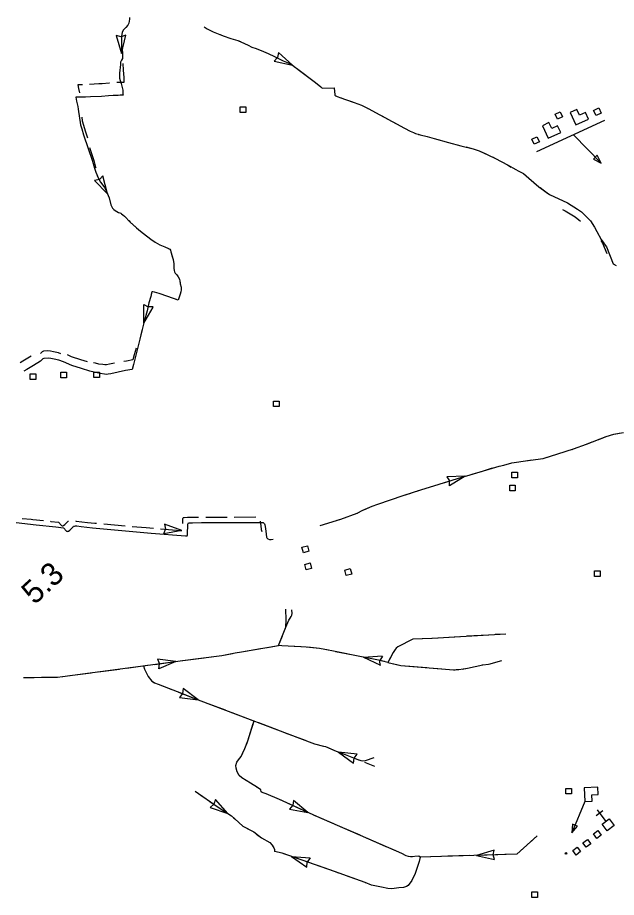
# Model space of a CAD drawing. Extents: x -160 to 6143532, y -375 to 762199.
# Drawn here: x -110.03 to -87.11, y -272.42 to -238.77 of the extents above; entities that cross this region are included whole.
import ezdxf

# ---------------------------------------------------------------- set-up
doc = ezdxf.new("R2010")
doc.units = 0
for name, color, linetype in [('Level 43', 7, 'Continuous'), ('Level 48', 7, 'Continuous'), ('Level 56', 7, 'Continuous'), ('Level 57', 7, 'Continuous'), ('Level 58', 7, 'Continuous')]:
    doc.layers.add(name, color=color, linetype=linetype)

msp = doc.modelspace()

# ---------------------------------------------------------------- linework, layer by layer
at = {"layer": 'Level 43'}
for p, q in [((-106.066, -239.503), (-106.25, -239.46)), ((-106.25, -239.46), (-106.046, -240.14)), ((-105.883, -239.449), (-106.064, -239.503)), ((-106.046, -240.14), (-105.883, -239.449)), ((-100.039, -240.112), (-100.079, -240.296)), ((-99.513, -240.588), (-100.039, -240.112)), ((-100.08, -240.298), (-100.207, -240.439)), ((-100.207, -240.439), (-99.513, -240.588)), ((-106.761, -244.829), (-106.896, -244.961)), ((-106.588, -245.518), (-106.761, -244.829)), ((-106.899, -244.962), (-107.082, -245.008)), ((-107.082, -245.008), (-106.588, -245.518)), ((-105.203, -249.75), (-105.036, -249.838)), ((-105.198, -250.454), (-105.192, -249.744)), ((-105.198, -250.454), (-104.838, -249.842)), ((-104.845, -249.832), (-105.033, -249.839)), ((-92.895, -256.305), (-93.604, -256.333)), ((-93.604, -256.333), (-93.503, -256.493)), ((-92.895, -256.305), (-93.495, -256.684)), ((-93.495, -256.684), (-93.503, -256.495)), ((-104.437, -258.517), (-104.373, -258.339)), ((-103.738, -258.391), (-104.437, -258.517)), ((-103.738, -258.391), (-104.406, -258.151)), ((-104.406, -258.151), (-104.373, -258.336)), ((-103.969, -263.401), (-104.673, -263.309)), ((-104.673, -263.309), (-104.6, -263.483)), ((-103.969, -263.401), (-104.624, -263.673)), ((-96.784, -263.235), (-96.076, -263.183)), ((-96.784, -263.235), (-96.145, -263.544)), ((-96.067, -263.19), (-96.159, -263.356)), ((-96.156, -263.547), (-96.159, -263.358)), ((-104.624, -263.673), (-104.6, -263.485)), ((-103.692, -264.437), (-103.714, -264.624)), ((-103.123, -264.861), (-103.692, -264.437)), ((-103.715, -264.627), (-103.828, -264.778)), ((-103.828, -264.778), (-103.123, -264.861)), ((-97.036, -266.946), (-97.741, -266.864)), ((-97.741, -266.864), (-97.171, -267.287)), ((-97.171, -267.287), (-97.15, -267.1)), ((-97.149, -267.097), (-97.036, -266.946)), ((-102.451, -268.671), (-102.513, -268.85)), ((-101.986, -269.208), (-102.451, -268.671)), ((-99.464, -268.71), (-99.498, -268.896)), ((-98.923, -269.169), (-99.464, -268.71)), ((-102.514, -268.852), (-102.657, -268.976)), ((-102.657, -268.976), (-101.986, -269.208)), ((-99.499, -268.898), (-99.622, -269.042)), ((-99.622, -269.042), (-98.923, -269.169)), ((-99.542, -270.859), (-98.955, -271.258)), ((-99.542, -270.859), (-98.834, -270.911)), ((-91.787, -270.609), (-92.466, -270.815)), ((-92.466, -270.815), (-91.775, -270.976)), ((-91.83, -270.793), (-91.787, -270.609)), ((-91.775, -270.976), (-91.83, -270.796)), ((-98.955, -271.258), (-98.941, -271.07)), ((-98.834, -270.911), (-98.941, -271.067))]:
    msp.add_line(p, q, dxfattribs=at)
for points in [[(-105.744, -238.772), (-105.748, -238.836), (-105.777, -238.984), (-105.805, -239.063), (-105.882, -239.146), (-105.982, -239.25), (-106.026, -239.338), (-106.055, -239.48), (-106.055, -239.593), (-106.051, -239.811), (-106.02, -240.105), (-106.014, -240.298), (-106.02, -240.343), (-106.048, -240.396), (-106.087, -240.478), (-106.093, -240.567), (-106.129, -240.898), (-106.13, -241.018), (-106.125, -241.088), (-106.107, -241.184), (-106.062, -241.295), (-105.995, -241.548), (-105.995, -241.688), (-105.992, -241.739), (-106.097, -241.742), (-106.183, -241.748), (-106.265, -241.75), (-106.369, -241.75), (-106.549, -241.762), (-106.821, -241.785), (-107.242, -241.804), (-107.425, -241.81), (-107.794, -241.821), (-107.779, -241.964), (-107.72, -242.177), (-107.71, -242.28), (-107.616, -242.869), (-107.575, -243.032), (-107.507, -243.251), (-107.162, -244.264), (-107.091, -244.53), (-107.035, -244.685), (-106.937, -244.925), (-106.854, -245.063), (-106.809, -245.136), (-106.708, -245.274), (-106.624, -245.427), (-106.526, -245.67), (-106.458, -245.935), (-106.426, -246.009), (-106.393, -246.065), (-106.373, -246.087), (-106.344, -246.115), (-106.296, -246.147), (-106.163, -246.226), (-106.122, -246.242), (-106.079, -246.255), (-106.052, -246.273), (-105.996, -246.316), (-105.937, -246.372), (-105.715, -246.591), (-105.386, -246.893), (-105.212, -247.033), (-104.929, -247.243), (-104.758, -247.36), (-104.583, -247.459), (-104.398, -247.545), (-104.255, -247.604), (-104.208, -247.633), (-104.18, -247.667), (-104.159, -247.732), (-104.074, -248.023), (-104.054, -248.189), (-104.051, -248.36), (-104.041, -248.442), (-104.023, -248.5), (-103.995, -248.551), (-103.939, -248.606), (-103.883, -248.683), (-103.838, -248.778), (-103.816, -248.853), (-103.802, -248.957), (-103.773, -249.078), (-103.765, -249.185)], [(-105.744, -238.772), (-105.748, -238.836), (-105.752, -238.858)], [(-105.847, -239.108), (-105.882, -239.146), (-105.982, -239.25), (-106.026, -239.338), (-106.055, -239.48), (-106.055, -239.593), (-106.051, -239.811), (-106.046, -239.859), (-106.046, -240.14)], [(-102.885, -239.125), (-102.772, -239.207), (-102.544, -239.313), (-102.165, -239.47), (-101.865, -239.568), (-101.594, -239.652), (-101.34, -239.761), (-101.2, -239.826), (-101.063, -239.903), (-100.903, -239.949), (-100.62, -240.072), (-100.443, -240.147), (-100.19, -240.264), (-99.968, -240.376), (-99.861, -240.424), (-99.67, -240.506), (-99.52, -240.582), (-99.449, -240.637), (-99.305, -240.749), (-98.675, -241.217), (-98.5, -241.355), (-98.424, -241.424), (-98.378, -241.471), (-97.907, -241.46), (-97.892, -241.724), (-97.881, -241.74), (-97.853, -241.763), (-97.794, -241.791), (-97.523, -241.886), (-97.144, -242.015), (-96.872, -242.126), (-96.606, -242.255), (-96.159, -242.491), (-95.218, -243.001), (-94.999, -243.11), (-94.871, -243.168), (-94.797, -243.199), (-94.702, -243.231), (-94.615, -243.258), (-94.349, -243.314), (-94.079, -243.394), (-93.538, -243.552)], [(-102.885, -239.125), (-102.772, -239.207), (-102.544, -239.313), (-102.527, -239.32)], [(-102.275, -239.424), (-102.165, -239.47), (-101.865, -239.568), (-101.594, -239.652), (-101.501, -239.692)], [(-101.252, -239.802), (-101.2, -239.826), (-101.063, -239.903), (-100.903, -239.949), (-100.62, -240.072), (-100.5, -240.123)], [(-100.251, -240.235), (-100.19, -240.264), (-99.968, -240.376), (-99.861, -240.424), (-99.67, -240.506), (-99.52, -240.582), (-99.513, -240.588)], [(-106.006, -240.524), (-105.986, -240.779), (-105.965, -241.058), (-105.965, -241.198), (-105.962, -241.249), (-106.068, -241.252), (-106.153, -241.258), (-106.227, -241.26)], [(-99.296, -240.755), (-98.675, -241.217), (-98.64, -241.245)], [(-107.545, -241.342), (-107.719, -241.347), (-107.703, -241.49), (-107.66, -241.644)], [(-106.506, -241.279), (-106.526, -241.28), (-106.797, -241.303), (-106.914, -241.309), (-107.28, -241.329)], [(-97.641, -241.845), (-97.523, -241.886), (-97.253, -241.978)], [(-97.253, -241.978), (-97.144, -242.015), (-96.872, -242.126), (-96.871, -242.126)], [(-96.626, -242.245), (-96.606, -242.255), (-96.159, -242.491), (-95.903, -242.63)], [(-107.575, -242.581), (-107.552, -242.725), (-107.512, -242.888), (-107.443, -243.108), (-107.355, -243.368)], [(-95.663, -242.76), (-95.218, -243.001), (-94.999, -243.11), (-94.936, -243.138)], [(-94.682, -243.237), (-94.615, -243.258), (-94.349, -243.314), (-94.079, -243.394), (-93.891, -243.449)], [(-93.629, -243.525), (-93.538, -243.552)], [(-93.538, -243.552), (-93.059, -243.671), (-92.591, -243.793), (-92.36, -243.873), (-92.001, -244.029), (-91.736, -244.156), (-91.276, -244.409), (-90.964, -244.586), (-90.868, -244.632), (-90.762, -244.683), (-90.665, -244.738), (-90.467, -244.919), (-90.079, -245.239), (-89.671, -245.543), (-88.978, -245.857), (-88.594, -246.093), (-88.451, -246.203), (-88.304, -246.338), (-88.101, -246.545), (-87.95, -246.793), (-87.861, -246.954), (-87.697, -247.257), (-87.621, -247.359), (-87.574, -247.422), (-87.494, -247.536), (-87.229, -248.185), (-87.119, -248.257)], [(-93.538, -243.552), (-93.141, -243.651)], [(-107.282, -243.738), (-107.114, -244.232), (-107.043, -244.498), (-107.036, -244.519)], [(-92.876, -243.719), (-92.591, -243.793), (-92.36, -243.873), (-92.103, -243.985)], [(-91.855, -244.099), (-91.736, -244.156), (-91.276, -244.409), (-91.135, -244.489)], [(-90.895, -244.619), (-90.868, -244.632), (-90.762, -244.683), (-90.665, -244.738), (-90.467, -244.919), (-90.242, -245.105)], [(-106.986, -244.806), (-106.937, -244.925), (-106.854, -245.063), (-106.809, -245.136), (-106.708, -245.274), (-106.624, -245.427), (-106.588, -245.518)], [(-90.03, -245.276), (-89.742, -245.49)], [(-106.499, -245.775), (-106.458, -245.935), (-106.426, -246.009), (-106.393, -246.065), (-106.373, -246.087), (-106.344, -246.115), (-106.296, -246.147), (-106.163, -246.226), (-106.122, -246.242), (-106.079, -246.255), (-106.052, -246.273), (-105.996, -246.316), (-105.971, -246.34)], [(-89.175, -246.113), (-89.069, -246.161), (-88.685, -246.397), (-88.542, -246.506), (-88.489, -246.555)], [(-105.776, -246.53), (-105.715, -246.591), (-105.477, -246.81)], [(-105.477, -246.81), (-105.386, -246.893), (-105.212, -247.033), (-105.161, -247.071)], [(-104.942, -247.234), (-104.929, -247.243), (-104.758, -247.36), (-104.583, -247.459), (-104.398, -247.545), (-104.255, -247.604), (-104.224, -247.623)], [(-87.712, -247.296), (-87.636, -247.404), (-87.475, -247.797)], [(-104.12, -247.867), (-104.074, -248.023), (-104.054, -248.189), (-104.051, -248.36), (-104.041, -248.442), (-104.023, -248.5), (-103.995, -248.551), (-103.939, -248.606), (-103.916, -248.637)], [(-103.812, -248.886), (-103.802, -248.957), (-103.773, -249.078), (-103.765, -249.185), (-103.777, -249.262), (-103.801, -249.355), (-103.875, -249.545), (-103.889, -249.578), (-103.986, -249.544)], [(-103.765, -249.185), (-103.777, -249.262), (-103.801, -249.355), (-103.875, -249.545), (-103.889, -249.578), (-104.281, -249.442), (-104.604, -249.327), (-104.785, -249.273), (-104.848, -249.256), (-104.871, -249.256), (-104.891, -249.264), (-104.897, -249.276), (-104.905, -249.303), (-104.928, -249.441), (-105, -249.686), (-105.068, -249.985), (-105.18, -250.389), (-105.307, -250.902), (-105.348, -251.077), (-105.599, -252.038), (-105.649, -252.23), (-105.893, -252.275), (-106.46, -252.392), (-106.567, -252.415), (-106.632, -252.42), (-106.708, -252.411), (-106.867, -252.39), (-106.988, -252.361), (-107.263, -252.292), (-107.587, -252.196), (-107.949, -252.073), (-108.272, -251.933), (-108.451, -251.87), (-108.633, -251.837), (-108.755, -251.811), (-108.858, -251.798), (-109.019, -251.806), (-109.064, -251.828), (-109.151, -251.907), (-109.42, -252.073), (-109.676, -252.23), (-109.785, -252.294)], [(-104.244, -249.455), (-104.281, -249.442), (-104.604, -249.327), (-104.785, -249.273), (-104.848, -249.256), (-104.871, -249.256), (-104.891, -249.264), (-104.897, -249.276), (-104.905, -249.303), (-104.921, -249.398)], [(-104.992, -249.661), (-105, -249.686), (-105.068, -249.985), (-105.18, -250.389), (-105.196, -250.455)], [(-105.262, -250.719), (-105.307, -250.902), (-105.348, -251.077), (-105.358, -251.118)], [(-108.375, -251.627), (-108.469, -251.593), (-108.651, -251.561), (-108.774, -251.534), (-108.876, -251.522), (-109.038, -251.53), (-109.083, -251.551), (-109.153, -251.615)], [(-107.349, -251.941), (-107.606, -251.864), (-107.968, -251.742), (-108.123, -251.674)], [(-105.494, -251.409), (-105.562, -251.669), (-105.612, -251.862), (-105.856, -251.907), (-105.957, -251.928)], [(-109.511, -251.725), (-109.568, -251.76), (-109.824, -251.917), (-109.933, -251.981)], [(-106.317, -251.983), (-106.515, -252.023), (-106.622, -252.047), (-106.687, -252.051), (-106.764, -252.042), (-106.922, -252.022), (-107.043, -251.992), (-107.122, -251.973)], [(-91.595, -255.922), (-91.423, -255.885), (-91.115, -255.802), (-90.583, -255.719), (-89.91, -255.635), (-89.636, -255.544), (-88.746, -255.269), (-88.256, -255.087), (-87.508, -254.795), (-87.209, -254.704), (-86.835, -254.637)], [(-87.786, -254.904), (-87.508, -254.795), (-87.209, -254.704), (-87.004, -254.668)], [(-88.808, -255.288), (-88.746, -255.269), (-88.256, -255.087), (-88.04, -255.003)], [(-89.799, -255.598), (-89.636, -255.544), (-89.069, -255.369)], [(-90.929, -255.773), (-90.583, -255.719), (-90.341, -255.689)], [(-98.445, -258.199), (-97.659, -257.955), (-97.038, -257.729), (-96.815, -257.61), (-96.46, -257.456), (-96.237, -257.377), (-95.275, -257.05), (-94.597, -256.835), (-93.19, -256.396), (-92.705, -256.253), (-91.595, -255.922)], [(-92.24, -256.114), (-91.847, -255.997)], [(-91.595, -255.922), (-91.423, -255.885), (-91.197, -255.824)], [(-93.677, -256.548), (-93.19, -256.396), (-92.894, -256.309)], [(-92.632, -256.231), (-92.24, -256.114)], [(-94.72, -256.874), (-94.597, -256.835), (-93.938, -256.629)], [(-95.757, -257.214), (-95.275, -257.05), (-94.98, -256.956)], [(-96.78, -257.595), (-96.46, -257.456), (-96.237, -257.377), (-96.016, -257.302)], [(-97.793, -257.997), (-97.659, -257.955), (-97.038, -257.729), (-97.022, -257.721)], [(-110.078, -258.085), (-109.319, -258.168), (-108.561, -258.245), (-108.277, -258.282), (-108.161, -258.409), (-108.13, -258.418), (-108.102, -258.42), (-108.076, -258.409), (-108.032, -258.37), (-107.907, -258.243), (-107.883, -258.225), (-107.856, -258.218), (-107.815, -258.205), (-107.762, -258.21), (-107.598, -258.236), (-107.161, -258.289), (-106.881, -258.313), (-104.914, -258.484), (-103.598, -258.594), (-103.566, -258.598), (-103.548, -258.598), (-103.535, -258.587), (-103.524, -258.565), (-103.522, -258.539), (-103.509, -258.14), (-103.504, -258.118), (-103.484, -258.1), (-103.465, -258.093), (-103.335, -258.091), (-102.991, -258.08), (-100.669, -258.078), (-100.625, -258.085), (-100.599, -258.107), (-100.579, -258.135), (-100.568, -258.17)], [(-109.854, -257.923), (-109.511, -257.961), (-109.447, -257.967)], [(-109.447, -257.967), (-109.04, -258.008)], [(-108.768, -258.036), (-108.752, -258.038), (-108.468, -258.075), (-108.352, -258.202), (-108.322, -258.211), (-108.293, -258.213), (-108.267, -258.202), (-108.223, -258.163), (-108.098, -258.035), (-108.083, -258.025)], [(-107.817, -258.024), (-107.789, -258.029), (-107.352, -258.081), (-107.072, -258.106), (-107.003, -258.112)], [(-103.706, -258.126), (-103.7, -257.932), (-103.695, -257.91), (-103.676, -257.893), (-103.656, -257.886), (-103.526, -257.884), (-103.51, -257.884)], [(-103.51, -257.884), (-103.182, -257.873), (-103.1, -257.873)], [(-102.827, -257.873), (-102.008, -257.872)], [(-101.735, -257.872), (-100.916, -257.871)], [(-100.744, -258.028), (-100.713, -258.211), (-100.703, -258.345), (-100.675, -258.427)], [(-106.731, -258.135), (-105.915, -258.206)], [(-105.643, -258.23), (-105.105, -258.277), (-104.827, -258.3)], [(-104.555, -258.323), (-103.79, -258.386), (-103.757, -258.391), (-103.739, -258.391), (-103.739, -258.39)], [(-100.568, -258.17), (-100.553, -258.234), (-100.522, -258.418), (-100.505, -258.644), (-100.489, -258.673), (-100.456, -258.703), (-100.382, -258.734), (-100.325, -258.732), (-100.241, -258.724)], [(-109.8, -264.012), (-108.735, -263.994), (-108.498, -263.994), (-108.314, -263.977), (-104.179, -263.428), (-103.718, -263.363), (-102.218, -263.165), (-101.697, -263.073), (-101.464, -263.034), (-100.048, -262.783), (-99.758, -262.086), (-99.649, -261.823), (-99.601, -261.744), (-99.557, -261.674), (-99.529, -261.62), (-99.525, -261.561), (-99.533, -261.425)], [(-99.79, -262.163), (-99.758, -262.086), (-99.748, -261.807), (-99.767, -261.402)], [(-100.462, -262.857), (-100.048, -262.783), (-99.895, -262.415)], [(-91.341, -262.347), (-94.165, -262.514), (-94.902, -262.54), (-95.472, -262.838), (-95.535, -262.89), (-95.581, -262.943), (-95.649, -263.054), (-95.857, -263.432), (-96.212, -263.344), (-96.868, -263.219), (-97.935, -263.008), (-98.477, -262.896), (-98.99, -262.85), (-99.181, -262.839), (-99.917, -262.8), (-100.048, -262.783)], [(-93.113, -262.452), (-93.931, -262.5)], [(-92.023, -262.387), (-92.84, -262.435)], [(-91.341, -262.347), (-91.75, -262.371)], [(-99.205, -262.838), (-99.917, -262.8), (-100.023, -262.787)], [(-95.25, -262.722), (-95.472, -262.838), (-95.535, -262.89), (-95.581, -262.943), (-95.649, -263.054), (-95.787, -263.306)], [(-94.203, -262.515), (-94.902, -262.54), (-95.008, -262.596)], [(-102.616, -263.218), (-102.218, -263.165), (-101.807, -263.092)], [(-101.538, -263.046), (-101.464, -263.034), (-100.731, -262.904)], [(-98.123, -262.97), (-98.477, -262.896), (-98.933, -262.856)], [(-97.454, -263.103), (-97.856, -263.024)], [(-97.052, -263.183), (-97.454, -263.103)], [(-104.781, -263.508), (-104.179, -263.428), (-103.969, -263.398)], [(-103.699, -263.36), (-103.293, -263.307)], [(-103.293, -263.307), (-102.887, -263.253)], [(-95.982, -263.401), (-96.212, -263.344), (-96.784, -263.235)], [(-95.857, -263.432), (-95.356, -263.547), (-93.339, -263.714), (-93.238, -263.709), (-93.146, -263.705), (-92.808, -263.657), (-92.225, -263.521), (-92.006, -263.503), (-91.909, -263.481), (-91.501, -263.363)], [(-95.857, -263.432), (-95.458, -263.523)], [(-91.939, -263.488), (-91.909, -263.481), (-91.501, -263.363)], [(-106.946, -263.795), (-106.134, -263.688)], [(-105.864, -263.652), (-105.051, -263.544)], [(-105.209, -263.565), (-105.178, -263.695), (-105.03, -263.971), (-104.892, -264.145), (-104.794, -264.216), (-104.651, -264.267), (-103.925, -264.549), (-103.123, -264.861), (-98.659, -266.549), (-98.32, -266.631), (-98.248, -266.646), (-98.161, -266.692), (-97.834, -266.83), (-97.497, -266.953), (-97.175, -267.086), (-97.001, -267.147), (-96.893, -267.183), (-96.817, -267.193), (-96.715, -267.183), (-96.387, -267.066)], [(-95.188, -263.561), (-94.372, -263.628)], [(-94.099, -263.651), (-93.339, -263.714), (-93.283, -263.711)], [(-93.011, -263.686), (-92.808, -263.657), (-92.225, -263.521), (-92.21, -263.519)], [(-109.8, -264.012), (-109.391, -264.005)], [(-109.118, -264.001), (-108.735, -263.994), (-108.498, -263.994), (-108.314, -263.977), (-108.3, -263.975)], [(-108.029, -263.939), (-107.217, -263.831)], [(-104.88, -264.153), (-104.794, -264.216), (-104.651, -264.267), (-104.129, -264.47)], [(-103.874, -264.569), (-103.123, -264.861), (-103.111, -264.865)], [(-102.855, -264.962), (-102.089, -265.252)], [(-101.834, -265.348), (-101.068, -265.638)], [(-90.149, -270.062), (-90.915, -270.768), (-94.627, -270.881), (-94.666, -270.847), (-94.988, -270.868), (-95.07, -270.858), (-95.157, -270.827), (-95.32, -270.74), (-98.572, -269.328), (-100.009, -268.679), (-100.515, -268.464), (-100.668, -268.413), (-100.709, -268.382), (-100.719, -268.3), (-100.847, -268.223), (-101.113, -268.054), (-101.451, -267.85), (-101.553, -267.753), (-101.624, -267.62), (-101.665, -267.476), (-101.67, -267.379), (-101.64, -267.251), (-101.578, -267.159), (-101.476, -267.026), (-101.328, -266.724), (-101.215, -266.438), (-100.98, -265.671)], [(-101.259, -266.549), (-101.215, -266.438), (-101.01, -265.769)], [(-100.812, -265.735), (-100.046, -266.024)], [(-99.791, -266.121), (-99.408, -266.266)], [(-99.408, -266.266), (-99.025, -266.411)], [(-101.572, -267.151), (-101.476, -267.026), (-101.365, -266.8)], [(-98.769, -266.507), (-98.659, -266.549), (-98.32, -266.631), (-98.248, -266.646), (-98.161, -266.692), (-97.995, -266.763)], [(-101.649, -267.534), (-101.665, -267.476), (-101.67, -267.379), (-101.64, -267.251), (-101.578, -267.159), (-101.572, -267.151)], [(-97.741, -266.864), (-97.497, -266.953), (-97.175, -267.086), (-97.001, -267.147), (-96.976, -267.156)], [(-96.756, -267.254), (-96.373, -267.399)], [(-100.846, -268.224), (-100.847, -268.223), (-101.113, -268.054), (-101.451, -267.85), (-101.529, -267.775)], [(-103.227, -268.362), (-102.353, -268.965), (-101.841, -269.303), (-101.713, -269.421), (-101.402, -269.697), (-100.993, -269.912), (-100.691, -270.147), (-100.379, -270.321), (-100.282, -270.423), (-100.226, -270.526), (-100.2, -270.587), (-100.19, -270.662)], [(-103.227, -268.362), (-102.89, -268.595)], [(-99.918, -268.719), (-100.009, -268.679), (-100.515, -268.464), (-100.668, -268.413), (-100.675, -268.408)], [(-102.665, -268.75), (-102.353, -268.965), (-101.986, -269.208)], [(-98.923, -269.169), (-99.669, -268.832)], [(-101.768, -269.371), (-101.713, -269.421), (-101.402, -269.697), (-101.111, -269.85)], [(-97.924, -269.61), (-98.572, -269.328), (-98.674, -269.282)], [(-96.922, -270.045), (-97.673, -269.718)], [(-100.883, -269.998), (-100.691, -270.147), (-100.379, -270.321), (-100.282, -270.423), (-100.244, -270.492)], [(-96.296, -270.317), (-96.671, -270.153)], [(-90.149, -270.062), (-90.45, -270.34)], [(-95.92, -270.48), (-96.296, -270.317)], [(-90.651, -270.525), (-90.915, -270.768), (-91.375, -270.782)], [(-94.627, -270.881), (-94.663, -271.051), (-94.811, -271.511), (-94.944, -271.777), (-95.077, -271.961), (-95.143, -272.007), (-95.261, -272.038), (-95.435, -272.058), (-95.701, -272.089), (-95.854, -272.079), (-96.099, -272.033), (-96.488, -271.946), (-96.723, -271.854), (-97.904, -271.429), (-99.903, -270.733), (-100.19, -270.662)], [(-99.8, -270.769), (-99.903, -270.733), (-100.19, -270.662)], [(-98.769, -271.128), (-99.542, -270.859)], [(-94.91, -270.863), (-94.988, -270.868), (-95.07, -270.858), (-95.157, -270.827), (-95.32, -270.74), (-95.67, -270.588)], [(-93.831, -270.857), (-94.627, -270.881), (-94.644, -270.866)], [(-92.739, -270.823), (-93.558, -270.848)], [(-91.647, -270.79), (-92.466, -270.815)], [(-94.627, -270.881), (-94.663, -271.051), (-94.735, -271.275)], [(-97.738, -271.489), (-97.904, -271.429), (-98.511, -271.218)], [(-96.71, -271.859), (-96.723, -271.854), (-97.481, -271.581)]]:
    msp.add_lwpolyline(points, dxfattribs=at)
at = {"layer": 'Level 56'}
for points in [[(-101.512, -242.405), (-101.512, -242.19), (-101.296, -242.19), (-101.296, -242.405)], [(-87.89, -242.515), (-87.981, -242.32), (-87.785, -242.229), (-87.695, -242.424)], [(-89.366, -242.657), (-89.457, -242.462), (-89.261, -242.371), (-89.17, -242.566)], [(-90.255, -243.617), (-90.346, -243.422), (-90.15, -243.331), (-90.059, -243.526)], [(-87.841, -244.036), (-87.992, -244.183), (-87.696, -244.337)], [(-108.378, -252.546), (-108.378, -252.331), (-108.162, -252.331), (-108.162, -252.546)], [(-107.116, -252.543), (-107.116, -252.327), (-106.9, -252.327), (-106.9, -252.543)], [(-109.546, -252.616), (-109.546, -252.4), (-109.33, -252.4), (-109.33, -252.616)], [(-100.236, -253.651), (-100.236, -253.436), (-100.02, -253.436), (-100.02, -253.651)], [(-91.108, -256.377), (-91.108, -256.162), (-90.892, -256.162), (-90.892, -256.377)], [(-91.195, -256.865), (-91.195, -256.649), (-90.979, -256.649), (-90.979, -256.865)], [(-98.881, -259.18), (-99.089, -259.236), (-99.145, -259.028), (-98.937, -258.972)], [(-98.774, -259.839), (-98.982, -259.894), (-99.038, -259.686), (-98.83, -259.63)], [(-97.241, -260.052), (-97.448, -260.108), (-97.504, -259.899), (-97.297, -259.843)], [(-87.737, -259.927), (-87.736, -260.142), (-87.952, -260.143), (-87.953, -259.928)], [(-89.049, -268.464), (-89.049, -268.249), (-88.833, -268.249), (-88.833, -268.464)], [(-87.865, -270.167), (-87.993, -269.994), (-87.819, -269.866), (-87.691, -270.039)], [(-88.653, -270.799), (-88.781, -270.626), (-88.608, -270.497), (-88.48, -270.67)], [(-88.264, -270.504), (-88.392, -270.331), (-88.219, -270.202), (-88.091, -270.376)], [(-90.35, -272.42), (-90.35, -272.205), (-90.134, -272.205), (-90.134, -272.42)]]:
    msp.add_lwpolyline(points, close=True, dxfattribs=at)
for points in [[(-87.565, -242.707), (-90.162, -243.912)], [(-87.696, -244.337), (-88.747, -243.255)]]:
    msp.add_lwpolyline(points, dxfattribs=at)
at = {"layer": 'Level 57'}
for p, q in [((-87.881, -269.283), (-87.632, -269.098)), ((-87.849, -269.066), (-87.517, -269.513))]:
    msp.add_line(p, q, dxfattribs=at)
msp.add_lwpolyline([(-87.46, -269.872), (-87.652, -269.613), (-87.383, -269.413), (-87.191, -269.673)], close=True, dxfattribs=at)
at = {"layer": 'Level 58'}
for points in [[(-88.659, -242.877), (-88.182, -242.656), (-88.299, -242.405), (-88.525, -242.509), (-88.629, -242.284), (-88.88, -242.401)], [(-89.72, -243.383), (-89.243, -243.162), (-89.36, -242.91), (-89.586, -243.015), (-89.69, -242.79), (-89.941, -242.906)], [(-88.341, -268.227), (-88.32, -268.752), (-88.043, -268.741), (-88.053, -268.493), (-87.805, -268.483), (-87.816, -268.206)], [(-88.594, -269.697), (-88.789, -269.617), (-88.812, -269.95)]]:
    msp.add_lwpolyline(points, close=True, dxfattribs=at)
msp.add_lwpolyline([(-88.32, -268.752), (-88.812, -269.95)], dxfattribs=at)
msp.add_circle((-89.041, -270.74), 0.031, dxfattribs=at)

# ---------------------------------------------------------------- texts
at = {"layer": 'Level 48'}
msp.add_text('5.3', height=0.8737, rotation=42.7896, dxfattribs=at).set_placement((-109.379, -261.256))

doc.saveas('drawing.dxf')
